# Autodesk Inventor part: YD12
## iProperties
Author: Administrator
Shininess: 73.0
PropertySet Name: _Private Model Information
Created: 2000-09
Part Number: YD12
Material: Steel, High Strength Low Alloy
Document SubType Name: Modeling
Designer: Administrator
Control State: 0
Master: False
Checked Out: False
PropertySet Name: Design Tracking Control
Density: 7.839999999999999
Volumn: 156.3078276218653
Area: 359.54789551344936
PropertySet Name: Model Information
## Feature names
1. Extrusion3
